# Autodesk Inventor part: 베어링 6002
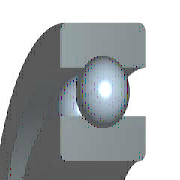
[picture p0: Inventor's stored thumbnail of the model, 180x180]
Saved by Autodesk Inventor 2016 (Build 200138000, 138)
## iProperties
IsCustomPart: 0
Created: 2015-10
Part Number: 베어링 6002
Material: Steel, Mild
Description: 깊은 그루브 볼 베어링
Document SubType Name: Modeling
Standard: KS B 2023
Designer: mdu
Standards Organization: KS
Language: ko-KR
Size Designation: 6002 - 15 x 32 x 9
Categories: <MemberInstance><Categories><Category DisplayName="샤프트 부품" InternalName="7f7aeb1f-a693-4053-b835-cee3144e0d98" Mnemonic="SHFT"><Category DisplayName="베어링" Inter
Density: 1 g/cm^3
Appearance: Steel
Author: mdu
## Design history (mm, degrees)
revolve "본체" stored, may be unused: angle "d6" = 90 deg
revolve "볼" stored, may be unused: angle "d7" = 90 deg
pattern_circular "IDS_ARRAYBALL[SIMPL:T]" dims angle "d3" = 360 deg
body "Solid1"
sketch "스케치" dims "d0" = 4.42 (= -0.26 x WD + 0.26 x BD)
  geometry: L1 (2.29, 11.75)-(6.71, 11.75); L2 (4.5, 11.75)-(4.5, 9.54); L3 (4.5, 11.75)-(4.5, 13.96); L4 (2.858, 10.271)-(0, 10.271); L5 (0, 7.5)-(9, 7.5); L6 (2.858, 13.229)-(0, 13.229); L7 (0, 16)-(9, 16); L8 (9, 7.5)-(9, 10.271); L9 (6.142, 10.271)-(9, 10.271); L10 (6.142, 13.229)-(9, 13.229); L11 (9, 16)-(9, 13.229); L12 (-1.4, 0)-(8.4, 0) reference; L13 (0, -0.3)-(0, 5.3) reference
  constraints: 22 end point, 4 point on line, 2 collinear, 2 perpendicular, 2 symmetric about line, 1 midpoint, 1 parallel, 14 other
  dimensions: "d9" = 15 diameter of L5 L12 (= WD); "d11" = 32 diameter of L7 L12 (= BD); "d12" = 9 distance between parallel lines of L8 L13 (= KB); "d13" = 20.542 diameter of L9 L12 (= 0.326 x BD + 0.674 x WD)
fillet "모깎기1" dims "d1" = 0.3 (= KRS)
other parameters: "WD" = 15 [user parameter; used in 5 equation terms], "BD" = 32 [user parameter; used in 5 equation terms], "KB" = 9 [user parameter; used in 1 equation term], "KRS" = 0.3 [user parameter; used in 1 equation term], "d4" = 0, "d5" = 0, "d8" = 0, "d14" = 0, "d15" = 0, "BBA" = 0 [user parameter], "BC0" = 2850000 [user parameter], "BC" = 5590000 [user parameter], "BR" = 16 (= 0.5 x BD) [user parameter], "WR" = 7.5 (= 0.5 x WD) [user parameter]
